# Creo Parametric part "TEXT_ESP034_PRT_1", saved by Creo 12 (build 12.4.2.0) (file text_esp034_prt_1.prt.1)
Units: Custom; MM, KILOGRAM, SECS

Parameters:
  PTC_WM_ITERATION = "0"
  PTC_WM_VERSION = "-.0"
  PTC_WM_LIFECYCLE_STATE = "In Work"
  PTC_WM_LIFECYCLE = "MO_CADDocument"
  PTC_WM_CREATED_BY = "Maximilian Roepper (Z0017RMS: MO)"
  PTC_WM_CREATED_ON = "18-Sep-26 11:36:42 AM"
  PTC_WM_MODIFIED_BY = "Maximilian Roepper (Z0017RMS: MO)"
  PTC_WM_MODIFIED_ON = "18-Sep-26 11:36:46 AM"
  PDMLINKNUMBER = "PDM000071454961"
  PTC_WM_NAME = "text_esp034_prt_1.prt"
  PTC_WM_NUMBER = "PDM000071454961"

Other parameters: WEIGHT, WEIGHT_FACTOR, WEIGHT_ADD, _MASS_TEMP, _DIFF_TEMP, MC_ERRORS, SUPPLIER

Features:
  1. coordinate system
  2. datum plane "PRT_YZ"
  3. datum plane "PRT_XY"
  4. datum plane "PRT_XZ"
  5. coordinate system
  6. datum axis
  7. datum axis
  8. datum axis
  9. coordinate system
  10. imported feature
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
Other named items: PRT, SIEMENS_MO, DRW_VIEW_ORG, PRT_X, PRT_Y, PRT_Z, CS0, ROUGH_GROB

Layers: 00_STD_CSYS-KSYS, 01_STD_PLANES-EBENEN, 02_STD_AXES-ACHSEN, 03_STD_CSYS-KSYS, 24_IMPORT_FEAT-IMPORT_KE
